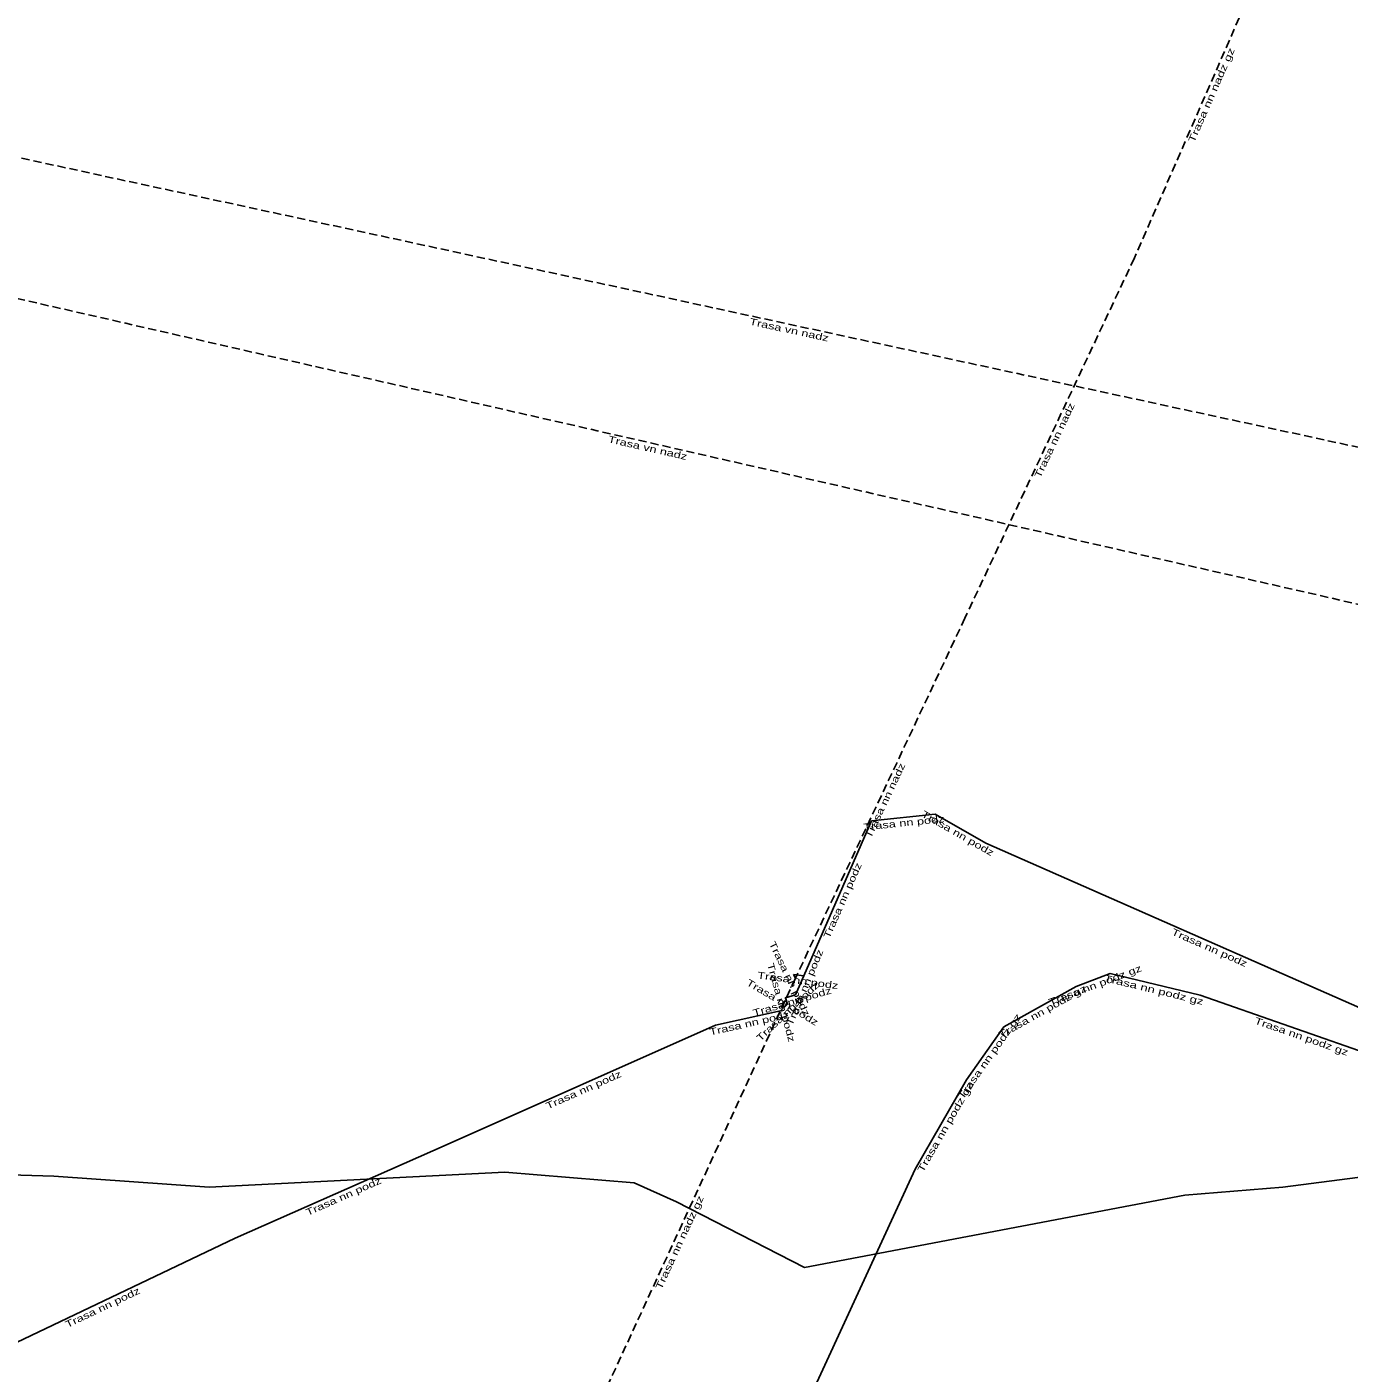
# Model space of a CAD drawing. Extents: x -648599 to -648043, y -1073975 to -1073476.
# Drawn here: x -648342.6 to -648245.5, y -1073665.4 to -1073566.6 of the extents above; entities that cross this region are included whole.
import ezdxf
from ezdxf.enums import TextEntityAlignment as Align

# ---------------------------------------------------------------- set-up
doc = ezdxf.new("R2010")
doc.units = 0
doc.header["$LTSCALE"] = 0.2
doc.linetypes.add('MEDIUM_DASHED', pattern=[4.5, 3, -1.5])
doc.layers.add('11', color=7, linetype='Continuous', lineweight=25)
doc.layers.add('21', color=7, linetype='MEDIUM_DASHED', lineweight=25)
doc.layers.add('20', color=7, linetype='Continuous')

msp = doc.modelspace()

# ---------------------------------------------------------------- linework, layer by layer
at = {"layer": '11', "linetype": 'MEDIUM_DASHED'}
for p, q in [((-648250.73, -1073559.28), (-648261.3, -1073583.51)), ((-648261.3, -1073583.51), (-648273.74, -1073609.945)), ((-648273.74, -1073609.945), (-648286.18, -1073636.379)), ((-648286.18, -1073636.379), (-648303.9, -1073674.83))]:
    msp.add_line(p, q, dxfattribs=at)
at = {"layer": '11'}
for p, q in [((-648280.59, -1073624.82), (-648275.93, -1073624.33)), ((-648275.93, -1073624.33), (-648272.2, -1073626.46)), ((-648272.2, -1073626.46), (-648239.06, -1073641.07)), ((-648286.32, -1073636.09), (-648286.18, -1073636.379)), ((-648285.57, -1073636.19), (-648286.32, -1073636.09)), ((-648263.09, -1073636.04), (-648265.57, -1073636.98)), ((-648256.47, -1073637.629), (-648263.09, -1073636.04)), ((-648265.57, -1073636.98), (-648270.89, -1073639.94)), ((-648286.9, -1073637.82), (-648286.959, -1073637.784)), ((-648286.9, -1073637.82), (-648286.16, -1073637.6)), ((-648286.77, -1073638.29), (-648286.9, -1073637.82)), ((-648241.34, -1073642.909), (-648256.47, -1073637.629)), ((-648292.04, -1073639.83), (-648287.27, -1073638.76)), ((-648287.27, -1073638.76), (-648286.77, -1073638.29)), ((-648270.89, -1073639.94), (-648273.63, -1073643.83)), ((-648273.63, -1073643.83), (-648277.4, -1073650.379)), ((-648277.4, -1073650.379), (-648294.46, -1073687.5))]:
    msp.add_line(p, q, dxfattribs=at)
for points in [[(-648286.16, -1073637.6), (-648285.57, -1073636.19), (-648280.59, -1073624.82)], [(-648347.1, -1073664.899), (-648327.28, -1073655.46), (-648311.73, -1073648.58), (-648292.04, -1073639.83)], [(-648230.02, -1073649.48), (-648238.7, -1073650.2), (-648250.4, -1073651.7), (-648257.6, -1073652.3), (-648285.5, -1073657.6), (-648294.9, -1073652.8), (-648298, -1073651.399), (-648307.5, -1073650.6), (-648329.2, -1073651.7), (-648340.6, -1073650.899), (-648350.3, -1073650.6)]]:
    msp.add_lwpolyline(points, dxfattribs=at)
at = {"layer": '21'}
msp.add_line((-648360.571, -1073572.382), (-648212.537, -1073604.395), dxfattribs=at)
msp.add_lwpolyline([(-648045.041, -1073653.534), (-648216.38, -1073615.425), (-648377.485, -1073578.688)], dxfattribs=at)

# ---------------------------------------------------------------- texts
at = {"layer": '20'}
for s, rotation, width, p in [('Trasa nn nadz gz', 66.431, 1.45, (-648255.4185, -1073571.6545)), ('Trasa vn nadz', 347.798, 1.4, (-648286.6913, -1073589.0235)), ('Trasa nn nadz', 64.799, 1.4, (-648266.9316, -1073597.0039)), ('Trasa vn nadz', 347.154, 1.4, (-648297.0761, -1073597.6889)), ('Trasa nn nadz', 64.799, 1.4, (-648279.3716, -1073623.4389)), ('Trasa nn podz', 330.272, 1.4, (-648274.3865, -1073625.9587)), ('Trasa nn podz', 6.003, 1.4, (-648278.1916, -1073625.2213)), ('Trasa nn podz', 66.347, 1.4, (-648282.4849, -1073630.7648)), ('Trasa nn podz', 336.209, 1.4, (-648255.8913, -1073634.3592)), ('Trasa nn podz', 295.769, 1.4, (-648286.8344, -1073636.5168)), ('Trasa nn podz', 67.294, 1.4, (-648285.2645, -1073637.145)), ('Trasa nn podz', 352.405, 1.4, (-648286.0305, -1073636.7834)), ('Trasa nn podz', 285.461, 1.4, (-648287.461, -1073638.2279)), ('Trasa nn podz gz', 20.758, 1.4, (-648264.0991, -1073637.1173)), ('Trasa nn podz gz', 346.494, 1.45, (-648259.9309, -1073637.4669)), ('Trasa nn podz', 329.323, 1.4, (-648287.261, -1073638.362)), ('Trasa nn podz', 16.557, 1.4, (-648286.3437, -1073638.3322)), ('Trasa nn podz', 43.229, 1.4, (-648286.5747, -1073638.9981)), ('Trasa nn podz gz', 29.091, 1.4, (-648267.914, -1073639.028)), ('Trasa nn podz', 12.643, 1.4, (-648289.5112, -1073639.9278)), ('Trasa nn podz gz', 54.84, 1.45, (-648271.7281, -1073642.2585)), ('Trasa nn podz gz', 340.762, 1.4, (-648249.1189, -1073640.8838)), ('Trasa nn podz', 23.96, 1.4, (-648301.621, -1073644.7993)), ('Trasa nn podz gz', 60.076, 1.45, (-648274.9504, -1073647.4292)), ('Trasa nn podz', 23.867, 1.4, (-648319.2417, -1073652.6143)), ('Trasa nn nadz gz', 65.257, 1.45, (-648294.4498, -1073655.8761)), ('Trasa nn podz', 25.468, 1.4, (-648336.91, -1073660.7663))]:
    msp.add_text(s, height=0.5, rotation=rotation, dxfattribs=dict(at, width=width)).set_placement(p, align=Align.CENTER)

doc.saveas('drawing.dxf')
